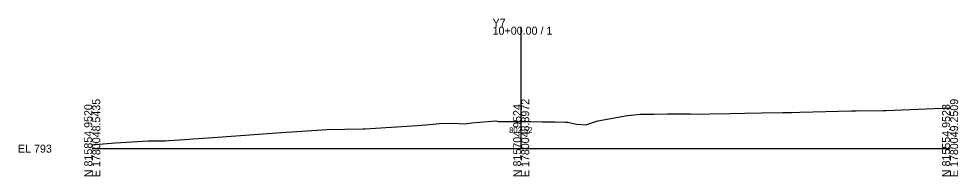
# Model space of a CAD drawing. Extents: x -26 to 2903, y -10 to 5536.
# Drawn here: x -25.7 to 302.8, y -9.7 to 45.6 of the extents above; entities that cross this region are included whole.
import ezdxf

# ---------------------------------------------------------------- set-up
doc = ezdxf.new("R2010")
doc.units = 0
for name, color, linetype in [('Exist Cross Section Cell', 7, 'Continuous'), ('Exist XS Center Line Elevation Label', 7, 'Continuous'), ('Exist XS Ground Line', 7, 'Continuous')]:
    doc.layers.add(name, color=color, linetype=linetype)

msp = doc.modelspace()

# ---------------------------------------------------------------- linework, layer by layer
at = {"layer": 'Exist Cross Section Cell'}
for p, q in [((150, 0), (150, 42.77)), ((0, 0), (150, 0)), ((150, 0), (300, 0))]:
    msp.add_line(p, q, dxfattribs=at)
at = {"layer": 'Exist XS Ground Line'}
for p, q in [((247.4, 12.75), (265.56, 13.25)), ((265.56, 13.25), (267.15, 13.26)), ((267.15, 13.26), (276.43, 13.36)), ((276.43, 13.36), (277.69, 13.34)), ((277.69, 13.34), (300, 14.26)), ((176.86, 9.7), (187.13, 11.66)), ((187.13, 11.66), (191.73, 12.06)), ((191.73, 12.06), (196.36, 12.13)), ((196.36, 12.13), (201.19, 12.15)), ((201.19, 12.15), (209.19, 12.16)), ((209.19, 12.16), (212.1, 12.12)), ((212.1, 12.12), (216.01, 12.23)), ((216.01, 12.23), (223.08, 12.37)), ((223.08, 12.37), (228.25, 12.48)), ((228.25, 12.48), (234.01, 12.6)), ((234.01, 12.6), (241.52, 12.66)), ((241.52, 12.66), (244.77, 12.67)), ((244.77, 12.67), (247.4, 12.75)), ((69.77, 5.9), (81.99, 6.77)), ((81.99, 6.77), (94.66, 6.89)), ((94.66, 6.89), (95.05, 6.89)), ((95.05, 6.89), (95.46, 6.91)), ((95.46, 6.91), (113.68, 8.15)), ((113.68, 8.15), (117.92, 8.42)), ((117.92, 8.42), (121.48, 8.8)), ((121.48, 8.8), (125.82, 8.88)), ((125.82, 8.88), (130.43, 8.73)), ((130.43, 8.73), (132.8, 9.02)), ((132.8, 9.02), (135.46, 9.3)), ((135.46, 9.3), (141.14, 9.7)), ((141.14, 9.7), (142.01, 9.53)), ((142.01, 9.53), (148.48, 9.53)), ((148.48, 9.53), (150, 9.52)), ((150, 9.52), (153.31, 9.49)), ((153.31, 9.49), (157.34, 9.4)), ((157.34, 9.4), (161.75, 9.36)), ((161.75, 9.36), (165.38, 9.25)), ((165.38, 9.25), (166.3, 9.27)), ((166.3, 9.27), (168.35, 8.82)), ((168.35, 8.82), (169.44, 8.64)), ((169.44, 8.64), (172.57, 8.35)), ((172.57, 8.35), (176.86, 9.7)), ((32.36, 3.19), (35.2, 3.44)), ((35.2, 3.44), (40.67, 3.8)), ((40.67, 3.8), (67.67, 5.75)), ((67.67, 5.75), (69.77, 5.9)), ((0, 1.3), (2.38, 1.51)), ((2.38, 1.51), (8.03, 2.04)), ((8.03, 2.04), (19.63, 2.71)), ((19.63, 2.71), (25.49, 2.77)), ((25.49, 2.77), (26.74, 2.9)), ((26.74, 2.9), (32.36, 3.19))]:
    msp.add_line(p, q, dxfattribs=at)

# ---------------------------------------------------------------- texts
at = {"layer": 'Exist Cross Section Cell'}
for s, p in [('Y7', (140, 42.77)), ('10+00.00 / 1', (140, 39.97)), ('EL 793', (-26, -1.4))]:
    msp.add_text(s, height=2.8, dxfattribs=at).set_placement(p)
for s, p in [('E 1780048.5435', (2.8, -10)), ('E 1780048.8972', (152.8, -10)), ('E 1780049.2509', (302.8, -10)), ('N 815854.9520', (0, -10)), ('N 815704.9524', (150, -10)), ('N 815554.9528', (300, -10))]:
    msp.add_text(s, height=2.8, rotation=90, dxfattribs=at).set_placement(p)
at = {"layer": 'Exist XS Center Line Elevation Label'}
msp.add_text('802.52', height=2, dxfattribs=at).set_placement((145.79, 5.52))

doc.saveas('drawing.dxf')
